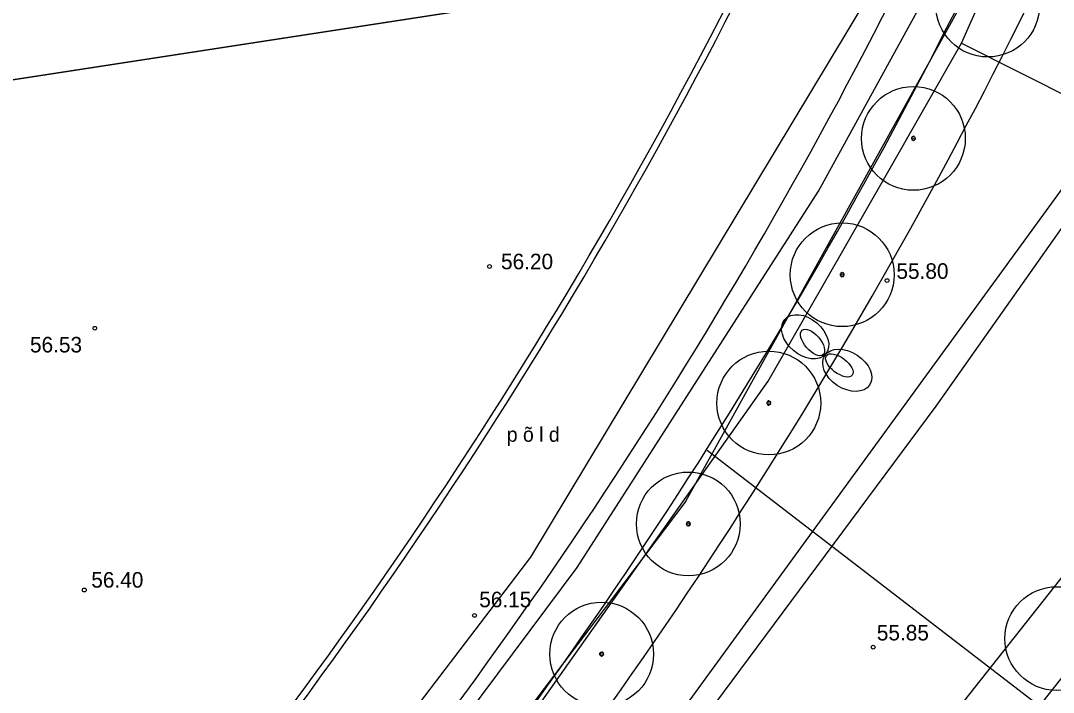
# Model space of a CAD drawing. Extents: x 9156 to 9809, y 2728 to 4000.
# Drawn here: x 9440.27 to 9490.03, y 3564.25 to 3596.6 of the extents above; entities that cross this region are included whole.
import ezdxf

# ---------------------------------------------------------------- set-up
doc = ezdxf.new("R2010")
doc.units = 0
for name, color, linetype in [('Level 11', 7, 'Continuous'), ('Level 12', 7, 'Continuous'), ('Level 14', 7, 'Continuous'), ('Level 15', 7, 'Continuous'), ('Level 16', 7, 'Continuous'), ('Level 17', 7, 'Continuous'), ('Level 18', 7, 'Continuous'), ('Level 54', 7, 'Continuous'), ('Level 56', 7, 'Continuous'), ('Level 6', 7, 'Continuous'), ('Level 7', 7, 'Continuous'), ('Level 8', 7, 'Continuous'), ('Level 9', 7, 'Continuous')]:
    doc.layers.add(name, color=color, linetype=linetype)

msp = doc.modelspace()

# ---------------------------------------------------------------- linework, layer by layer
at = {"layer": 'Level 11'}
for p, q in [((9417.595, 3590.318), (9473.096, 3598.869)), ((9473.096, 3598.869), (9417.595, 3590.318))]:
    msp.add_line(p, q, dxfattribs=at)
msp.add_arc((9257.773, 3708.522), 243.4, 317.80433, 332.882, dxfattribs=at)
msp.add_arc((9257.773, 3708.522), 243.4, 317.80433, 332.882, dxfattribs=at)
at = {"layer": 'Level 12'}
for p, q in [((9472.329, 3573.455), (9489.968, 3605.272)), ((9473.356, 3575.917), (9493.592, 3560.357)), ((9472.329, 3573.455), (9435.481, 3524.854))]:
    msp.add_line(p, q, dxfattribs=at)
at = {"layer": 'Level 14'}
for p, q in [((9484.383, 3578.032), (9498.336, 3597.816)), ((9427.489, 3501.526), (9484.383, 3578.032))]:
    msp.add_line(p, q, dxfattribs=at)
at = {"layer": 'Level 15'}
for p, q in [((9485.606, 3595.511), (9494.516, 3615.604)), ((9481.981, 3589.166), (9485.606, 3595.511)), ((9485.606, 3595.511), (9509.617, 3583.425)), ((9476.288, 3579.24), (9481.981, 3589.166)), ((9458.77, 3554.464), (9476.288, 3579.24))]:
    msp.add_line(p, q, dxfattribs=at)
at = {"layer": 'Level 16'}
msp.add_line((9469.372, 3559.57), (9501.086, 3603.087), dxfattribs=at)
at = {"layer": 'Level 17'}
for p, q in [((9478.72, 3588.396), (9484.61, 3599.122)), ((9467.092, 3570.267), (9478.72, 3588.396)), ((9504.212, 3582.406), (9456.099, 3521.498)), ((9458.182, 3558.332), (9467.092, 3570.267))]:
    msp.add_line(p, q, dxfattribs=at)
for radius in [243.4, 246.4]:
    msp.add_arc((9265.261, 3707.934), radius, 321.41014, 335.20045, dxfattribs=at)
at = {"layer": 'Level 18'}
msp.add_line((9501.857, 3584.265), (9455.749, 3525.895), dxfattribs=at)
msp.add_arc((9265.261, 3707.934), 249.4, 321.41014, 335.20045, dxfattribs=at)
at = {"layer": 'Level 54'}
for centre in [(9462.864, 3584.761), (9482.02, 3584.083), (9443.844, 3581.788), (9443.338, 3569.179), (9462.141, 3567.955), (9481.353, 3566.426)]:
    msp.add_circle(centre, 0.0909, dxfattribs=at)
at = {"layer": 'Level 56'}
for p, q in [((9501.857, 3584.265), (9455.749, 3525.895)), ((9504.212, 3582.406), (9456.099, 3521.498))]:
    msp.add_line(p, q, dxfattribs=at)
for radius in [243.4, 246.4, 249.4]:
    msp.add_arc((9265.261, 3707.934), radius, 321.41014, 335.20045, dxfattribs=at)
at = {"layer": 'Level 6'}
msp.add_arc((9257.773, 3708.522), 243.702, 317.80433, 332.882, dxfattribs=at)
at = {"layer": 'Level 7'}
for p, q in [((9464.86, 3570.761), (9481.208, 3597.915)), ((9428.759, 3523.586), (9464.86, 3570.761))]:
    msp.add_line(p, q, dxfattribs=at)
at = {"layer": 'Level 8'}
for centre, major_axis, ratio in [((9478.073, 3581.375), (0.986, -0.837), 0.674652), ((9478.073, 3581.375), (0.986, -0.837), 0.674652), ((9478.073, 3581.375), (0.986, -0.837), 0.674652), ((9478.073, 3581.375), (0.986, -0.837), 0.674652), ((9478.432, 3581.105), (0.507, -0.589), 0.486914), ((9478.432, 3581.105), (0.507, -0.589), 0.486914), ((9478.432, 3581.105), (0.507, -0.589), 0.486914), ((9478.432, 3581.105), (0.507, -0.589), 0.486914), ((9480.1, 3579.763), (-1.081, 0.71), 0.674652), ((9480.1, 3579.763), (-1.081, 0.71), 0.674652), ((9480.1, 3579.763), (-1.081, 0.71), 0.674652), ((9480.1, 3579.763), (-1.081, 0.71), 0.674652), ((9479.722, 3579.997), (-0.62, 0.47), 0.486914), ((9479.722, 3579.997), (-0.62, 0.47), 0.486914), ((9479.722, 3579.997), (-0.62, 0.47), 0.486914), ((9479.722, 3579.997), (-0.62, 0.47), 0.486914)]:
    msp.add_ellipse(centre, major_axis=major_axis, ratio=ratio, dxfattribs=at)
at = {"layer": 'Level 9'}
for p, q in [((9483.212, 3590.946), (9483.19, 3590.949)), ((9483.19, 3590.92), (9483.211, 3590.924)), ((9483.198, 3590.976), (9483.218, 3590.968)), ((9483.218, 3590.902), (9483.198, 3590.892)), ((9483.213, 3590.869), (9483.23, 3590.883)), ((9483.23, 3590.987), (9483.214, 3591)), ((9483.235, 3591.019), (9483.247, 3591.001)), ((9483.247, 3590.868), (9483.235, 3590.85)), ((9483.268, 3591.01), (9483.261, 3591.031)), ((9483.261, 3590.838), (9483.267, 3590.859)), ((9483.3, 3590.933), (9483.279, 3590.933)), ((9483.29, 3590.856), (9483.289, 3590.834)), ((9483.29, 3591.035), (9483.29, 3591.013)), ((9483.29, 3590.923), (9483.29, 3590.944)), ((9483.311, 3591.01), (9483.317, 3591.031)), ((9483.317, 3590.838), (9483.312, 3590.859)), ((9483.332, 3590.868), (9483.344, 3590.85)), ((9483.344, 3591.019), (9483.333, 3591)), ((9483.349, 3590.986), (9483.366, 3591)), ((9483.366, 3590.869), (9483.35, 3590.884)), ((9483.381, 3590.976), (9483.362, 3590.967)), ((9483.362, 3590.902), (9483.382, 3590.894)), ((9483.368, 3590.946), (9483.389, 3590.949)), ((9483.389, 3590.921), (9483.368, 3590.925)), ((9479.781, 3584.377), (9479.759, 3584.38)), ((9479.759, 3584.352), (9479.78, 3584.355)), ((9479.767, 3584.408), (9479.787, 3584.4)), ((9479.787, 3584.333), (9479.767, 3584.323)), ((9479.782, 3584.3), (9479.799, 3584.315)), ((9479.799, 3584.418), (9479.783, 3584.432)), ((9479.804, 3584.45), (9479.816, 3584.432)), ((9479.816, 3584.299), (9479.804, 3584.281)), ((9479.837, 3584.442), (9479.83, 3584.462)), ((9479.83, 3584.269), (9479.836, 3584.29)), ((9479.869, 3584.365), (9479.848, 3584.365)), ((9479.859, 3584.287), (9479.858, 3584.265)), ((9479.859, 3584.466), (9479.859, 3584.445)), ((9479.859, 3584.354), (9479.859, 3584.375)), ((9479.88, 3584.442), (9479.886, 3584.463)), ((9479.886, 3584.269), (9479.881, 3584.29)), ((9479.901, 3584.299), (9479.913, 3584.281)), ((9479.912, 3584.451), (9479.902, 3584.432)), ((9479.918, 3584.418), (9479.935, 3584.432)), ((9479.935, 3584.301), (9479.919, 3584.315)), ((9479.95, 3584.407), (9479.931, 3584.398)), ((9479.931, 3584.334), (9479.951, 3584.325)), ((9479.937, 3584.377), (9479.958, 3584.381)), ((9479.958, 3584.352), (9479.937, 3584.356)), ((9476.232, 3578.228), (9476.252, 3578.219)), ((9476.264, 3578.238), (9476.247, 3578.252)), ((9476.269, 3578.27), (9476.28, 3578.252)), ((9476.301, 3578.261), (9476.295, 3578.282)), ((9476.323, 3578.286), (9476.323, 3578.264)), ((9476.344, 3578.261), (9476.351, 3578.282)), ((9476.377, 3578.271), (9476.366, 3578.252)), ((9476.382, 3578.238), (9476.399, 3578.252)), ((9476.415, 3578.227), (9476.395, 3578.218)), ((9476.245, 3578.197), (9476.224, 3578.2)), ((9476.224, 3578.172), (9476.245, 3578.175)), ((9476.251, 3578.153), (9476.232, 3578.143)), ((9476.247, 3578.12), (9476.263, 3578.134)), ((9476.281, 3578.119), (9476.269, 3578.101)), ((9476.294, 3578.089), (9476.3, 3578.11)), ((9476.334, 3578.185), (9476.313, 3578.185)), ((9476.323, 3578.107), (9476.322, 3578.085)), ((9476.323, 3578.174), (9476.323, 3578.195)), ((9476.351, 3578.089), (9476.345, 3578.11)), ((9476.365, 3578.119), (9476.377, 3578.101)), ((9476.4, 3578.121), (9476.384, 3578.135)), ((9476.395, 3578.154), (9476.415, 3578.145)), ((9476.401, 3578.197), (9476.423, 3578.201)), ((9476.423, 3578.172), (9476.401, 3578.176)), ((9472.367, 3572.375), (9472.345, 3572.378)), ((9472.345, 3572.349), (9472.366, 3572.353)), ((9472.353, 3572.405), (9472.373, 3572.397)), ((9472.373, 3572.331), (9472.353, 3572.321)), ((9472.368, 3572.298), (9472.385, 3572.312)), ((9472.385, 3572.415), (9472.369, 3572.429)), ((9472.39, 3572.448), (9472.402, 3572.429)), ((9472.402, 3572.297), (9472.39, 3572.279)), ((9472.423, 3572.439), (9472.416, 3572.46)), ((9472.416, 3572.267), (9472.422, 3572.288)), ((9472.455, 3572.362), (9472.434, 3572.362)), ((9472.445, 3572.284), (9472.444, 3572.263)), ((9472.445, 3572.464), (9472.445, 3572.442)), ((9472.445, 3572.352), (9472.445, 3572.373)), ((9472.466, 3572.439), (9472.472, 3572.46)), ((9472.472, 3572.267), (9472.467, 3572.288)), ((9472.487, 3572.297), (9472.499, 3572.278)), ((9472.498, 3572.448), (9472.488, 3572.429)), ((9472.504, 3572.415), (9472.521, 3572.429)), ((9472.521, 3572.298), (9472.505, 3572.313)), ((9472.536, 3572.405), (9472.517, 3572.395)), ((9472.517, 3572.331), (9472.537, 3572.322)), ((9472.523, 3572.374), (9472.544, 3572.378)), ((9472.544, 3572.35), (9472.523, 3572.353)), ((9468.19, 3566.105), (9468.168, 3566.108)), ((9468.168, 3566.079), (9468.19, 3566.083)), ((9468.176, 3566.135), (9468.196, 3566.127)), ((9468.196, 3566.06), (9468.176, 3566.051)), ((9468.191, 3566.028), (9468.208, 3566.042)), ((9468.208, 3566.145), (9468.192, 3566.159)), ((9468.213, 3566.178), (9468.225, 3566.159)), ((9468.225, 3566.027), (9468.213, 3566.009)), ((9468.246, 3566.169), (9468.239, 3566.19)), ((9468.239, 3565.997), (9468.245, 3566.018)), ((9468.278, 3566.092), (9468.257, 3566.092)), ((9468.268, 3566.014), (9468.267, 3565.993)), ((9468.268, 3566.194), (9468.268, 3566.172)), ((9468.268, 3566.082), (9468.268, 3566.103)), ((9468.289, 3566.169), (9468.295, 3566.19)), ((9468.295, 3565.996), (9468.29, 3566.017)), ((9468.31, 3566.026), (9468.322, 3566.008)), ((9468.322, 3566.178), (9468.311, 3566.159)), ((9468.327, 3566.145), (9468.344, 3566.159)), ((9468.345, 3566.028), (9468.328, 3566.043)), ((9468.359, 3566.135), (9468.34, 3566.125)), ((9468.34, 3566.061), (9468.36, 3566.052)), ((9468.346, 3566.104), (9468.367, 3566.108)), ((9468.367, 3566.08), (9468.346, 3566.083))]:
    msp.add_line(p, q, dxfattribs=at)
for centre in [(9486.87, 3597.353), (9483.29, 3590.933), (9479.859, 3584.365), (9476.323, 3578.185), (9472.445, 3572.362), (9490.197, 3566.838), (9468.268, 3566.092)]:
    msp.add_circle(centre, 2.5, dxfattribs=at)
for centre, radius, start, end in [((9483.29, 3590.934), 0.101, 155.3123, 171.7042), ((9483.29, 3590.934), 0.101, 187.9671, 204.8625), ((9483.29, 3590.934), 0.0788, 171.5431, 187.6203), ((9483.29, 3590.934), 0.101, 220.7122, 237.1166), ((9483.29, 3590.934), 0.101, 122.8434, 139.0222), ((9483.29, 3590.934), 0.0788, 138.6432, 154.5795), ((9483.29, 3590.934), 0.0788, 204.4529, 220.4774), ((9483.29, 3590.934), 0.0788, 105.9559, 123.0564), ((9483.29, 3590.934), 0.0788, 237.451, 253.0843), ((9483.29, 3590.934), 0.101, 90.0356, 106.342), ((9483.29, 3590.934), 0.101, 253.2952, 269.5718), ((9483.29, 3590.934), 0.0788, 74.31, 90.043), ((9483.29, 3590.934), 0.0788, 269.9461, 286.3473), ((9483.29, 3590.934), 0.101, 57.6108, 74.1981), ((9483.29, 3590.934), 0.101, 285.972, 302.5562), ((9483.29, 3590.934), 0.0788, 302.254, 320.086), ((9483.29, 3590.934), 0.0788, 41.2062, 56.7795), ((9483.29, 3590.934), 0.0788, 8.0619, 24.0332), ((9483.29, 3590.934), 0.0788, 336.0557, 352.7558), ((9483.29, 3590.934), 0.101, 24.5394, 40.9852), ((9483.29, 3590.934), 0.101, 319.7777, 336.0738), ((9483.29, 3590.934), 0.101, 352.27, 8.583), ((9479.859, 3584.366), 0.101, 155.3123, 171.7042), ((9479.859, 3584.366), 0.101, 187.9671, 204.8625), ((9479.859, 3584.366), 0.0788, 171.5431, 187.6203), ((9479.859, 3584.366), 0.101, 220.7122, 237.1166), ((9479.859, 3584.366), 0.101, 122.8434, 139.0222), ((9479.859, 3584.366), 0.0788, 138.6432, 154.5795), ((9479.859, 3584.366), 0.0788, 204.4529, 220.4774), ((9479.859, 3584.366), 0.0788, 105.9559, 123.0564), ((9479.859, 3584.366), 0.0788, 237.451, 253.0843), ((9479.859, 3584.366), 0.101, 90.0356, 106.342), ((9479.859, 3584.366), 0.101, 253.2952, 269.5718), ((9479.859, 3584.366), 0.0788, 74.31, 90.043), ((9479.859, 3584.366), 0.0788, 269.9461, 286.3473), ((9479.859, 3584.366), 0.101, 57.6108, 74.1981), ((9479.859, 3584.366), 0.101, 285.972, 302.5562), ((9479.859, 3584.366), 0.0788, 302.254, 320.086), ((9479.859, 3584.366), 0.0788, 41.2062, 56.7795), ((9479.859, 3584.366), 0.0788, 8.0619, 24.0332), ((9479.859, 3584.366), 0.0788, 336.0557, 352.7558), ((9479.859, 3584.366), 0.101, 24.5394, 40.9852), ((9479.859, 3584.366), 0.101, 319.7777, 336.0738), ((9479.859, 3584.366), 0.101, 352.27, 8.583), ((9476.323, 3578.186), 0.101, 155.3123, 171.7042), ((9476.323, 3578.186), 0.101, 122.8434, 139.0222), ((9476.323, 3578.186), 0.0788, 138.6432, 154.5795), ((9476.323, 3578.186), 0.0788, 105.9559, 123.0564), ((9476.323, 3578.186), 0.101, 90.0356, 106.342), ((9476.323, 3578.186), 0.0788, 74.31, 90.043), ((9476.323, 3578.186), 0.101, 57.6108, 74.1981), ((9476.323, 3578.186), 0.0788, 41.2062, 56.7795), ((9476.323, 3578.186), 0.0788, 8.0619, 24.0332), ((9476.323, 3578.186), 0.101, 24.5394, 40.9852), ((9476.323, 3578.186), 0.101, 187.9671, 204.8625), ((9476.323, 3578.186), 0.0788, 171.5431, 187.6203), ((9476.323, 3578.186), 0.101, 220.7122, 237.1166), ((9476.323, 3578.186), 0.0788, 204.4529, 220.4774), ((9476.323, 3578.186), 0.0788, 237.451, 253.0843), ((9476.323, 3578.186), 0.101, 253.2952, 269.5718), ((9476.323, 3578.186), 0.0788, 269.9461, 286.3473), ((9476.323, 3578.186), 0.101, 285.972, 302.5562), ((9476.323, 3578.186), 0.0788, 302.254, 320.086), ((9476.323, 3578.186), 0.0788, 336.0557, 352.7558), ((9476.323, 3578.186), 0.101, 319.7777, 336.0738), ((9476.323, 3578.186), 0.101, 352.27, 8.583), ((9472.445, 3572.363), 0.101, 155.3123, 171.7042), ((9472.445, 3572.363), 0.101, 187.9671, 204.8625), ((9472.445, 3572.363), 0.0788, 171.5431, 187.6203), ((9472.445, 3572.363), 0.101, 220.7122, 237.1166), ((9472.445, 3572.363), 0.101, 122.8434, 139.0222), ((9472.445, 3572.363), 0.0788, 138.6432, 154.5795), ((9472.445, 3572.363), 0.0788, 204.4529, 220.4774), ((9472.445, 3572.363), 0.0788, 105.9559, 123.0564), ((9472.445, 3572.363), 0.0788, 237.451, 253.0843), ((9472.445, 3572.363), 0.101, 90.0356, 106.342), ((9472.445, 3572.363), 0.101, 253.2952, 269.5718), ((9472.445, 3572.363), 0.0788, 74.31, 90.043), ((9472.445, 3572.363), 0.0788, 269.9461, 286.3473), ((9472.445, 3572.363), 0.101, 57.6108, 74.1981), ((9472.445, 3572.363), 0.101, 285.972, 302.5562), ((9472.445, 3572.363), 0.0788, 302.254, 320.086), ((9472.445, 3572.363), 0.0788, 41.2062, 56.7795), ((9472.445, 3572.363), 0.0788, 8.0619, 24.0332), ((9472.445, 3572.363), 0.0788, 336.0557, 352.7558), ((9472.445, 3572.363), 0.101, 24.5394, 40.9852), ((9472.445, 3572.363), 0.101, 319.7777, 336.0738), ((9472.445, 3572.363), 0.101, 352.27, 8.583), ((9468.268, 3566.093), 0.101, 155.3123, 171.7042), ((9468.268, 3566.093), 0.101, 187.9671, 204.8625), ((9468.268, 3566.093), 0.0788, 171.5431, 187.6203), ((9468.268, 3566.093), 0.101, 220.7122, 237.1166), ((9468.268, 3566.093), 0.101, 122.8434, 139.0222), ((9468.268, 3566.093), 0.0788, 138.6432, 154.5795), ((9468.268, 3566.093), 0.0788, 204.4529, 220.4774), ((9468.268, 3566.093), 0.0788, 105.9559, 123.0564), ((9468.268, 3566.093), 0.0788, 237.451, 253.0843), ((9468.268, 3566.093), 0.101, 90.0356, 106.342), ((9468.268, 3566.093), 0.101, 253.2952, 269.5718), ((9468.268, 3566.093), 0.0788, 74.31, 90.043), ((9468.268, 3566.093), 0.0788, 269.9461, 286.3473), ((9468.268, 3566.093), 0.101, 57.6108, 74.1981), ((9468.268, 3566.093), 0.101, 285.972, 302.5562), ((9468.268, 3566.093), 0.0788, 302.254, 320.086), ((9468.268, 3566.093), 0.0788, 41.2062, 56.7795), ((9468.268, 3566.093), 0.0788, 8.0619, 24.0332), ((9468.268, 3566.093), 0.0788, 336.0557, 352.7558), ((9468.268, 3566.093), 0.101, 24.5394, 40.9852), ((9468.268, 3566.093), 0.101, 319.7777, 336.0738), ((9468.268, 3566.093), 0.101, 352.27, 8.583)]:
    msp.add_arc(centre, radius, start, end, dxfattribs=at)

# ---------------------------------------------------------------- texts
at = {"layer": 'Level 54'}
for s, height, p in [('56.20', 0.75, (9463.419, 3584.627)), ('55.80', 0.75, (9482.471, 3584.167)), ('56.53', 0.75, (9440.722, 3580.621)), ('p õ l d', 0.7, (9463.696, 3576.32)), ('56.40', 0.75, (9443.676, 3569.293)), ('56.15', 0.75, (9462.368, 3568.347)), ('55.85', 0.75, (9481.526, 3566.749))]:
    msp.add_text(s, height=height, dxfattribs=at).set_placement(p)

doc.saveas('drawing.dxf')
